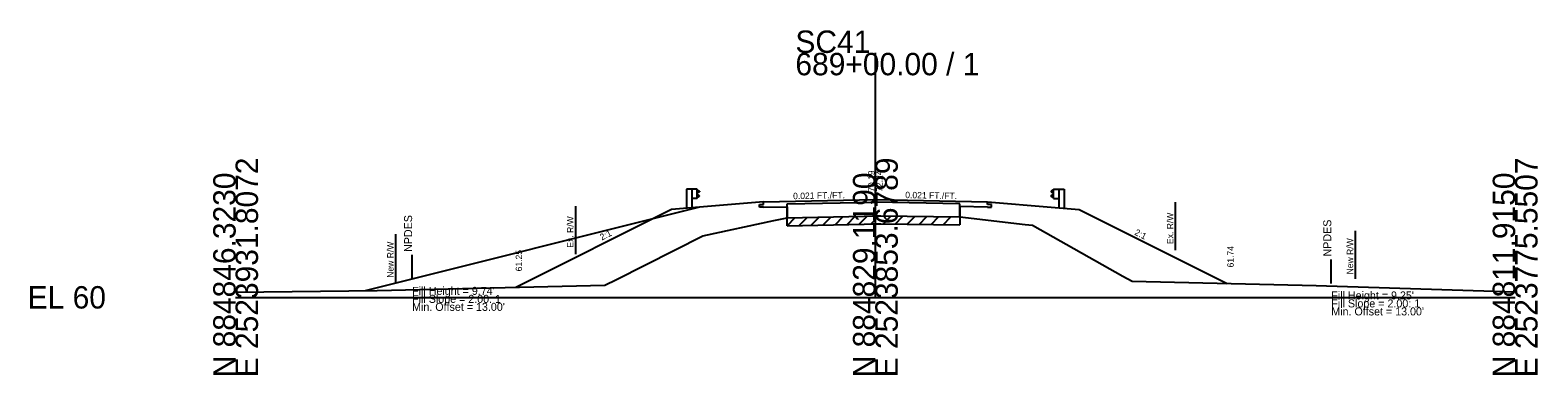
# Model space of a CAD drawing. Extents: x -26 to 183, y -10 to 24021.
# Drawn here: x -25.7 to 162.8, y 16490.3 to 16533.4 of the extents above; entities that cross this region are included whole.
import ezdxf

# ---------------------------------------------------------------- set-up
doc = ezdxf.new("R2010")
doc.units = 0
for name, color, linetype in [('RD_GPK_XS_Cell', 7, 'Continuous'), ('RD_XS_Base', 7, 'Continuous'), ('RD_XS_Buildup', 7, 'Continuous'), ('RD_XS_EarthShd', 7, 'Continuous'), ('RD_XS_ExGround', 7, 'Continuous'), ('RD_XS_ExPaveRet', 7, 'Continuous'), ('RD_XS_ExRW', 7, 'Continuous'), ('RD_XS_GR', 7, 'Continuous'), ('RD_XS_NewRW', 7, 'Continuous'), ('RD_XS_NPDES', 7, 'Continuous'), ('RD_XS_Pave', 7, 'Continuous'), ('RD_XS_TieSlope', 7, 'Continuous'), ('RD_XS_TX_Elev_EX', 7, 'Continuous'), ('RD_XS_TX_Elev_PR', 7, 'Continuous'), ('RD_XS_TX_Slope', 7, 'Continuous'), ('RD_XS_TX_Warning', 7, 'Continuous')]:
    doc.layers.add(name, color=color, linetype=linetype)

msp = doc.modelspace()

# ---------------------------------------------------------------- linework, layer by layer
at = {"layer": 'RD_GPK_XS_Cell'}
for p, q in [((80, 16500), (80, 16530.57)), ((0, 16500), (80, 16500)), ((80, 16500), (160, 16500))]:
    msp.add_line(p, q, dxfattribs=at)
at = {"layer": 'RD_XS_Base'}
for p, q in [((66, 16511.27), (68.96, 16511.33)), ((68.96, 16511.33), (68.96, 16509.94)), ((90.58, 16511.34), (90.58, 16510.05)), ((94, 16511.27), (90.58, 16511.34))]:
    msp.add_line(p, q, dxfattribs=at)
at = {"layer": 'RD_XS_Buildup'}
for p, q in [((68.96, 16511.69), (80, 16511.92)), ((68.96, 16509.94), (68.96, 16511.69)), ((90.58, 16511.7), (80, 16511.92)), ((90.58, 16510.05), (90.58, 16511.7))]:
    msp.add_line(p, q, dxfattribs=at)
at = {"layer": 'RD_XS_EarthShd'}
for p, q in [((66, 16511.95), (58, 16511.28)), ((94, 16511.95), (102, 16511.28)), ((58, 16511.28), (54.5, 16510.99)), ((102, 16511.28), (105.5, 16510.99))]:
    msp.add_line(p, q, dxfattribs=at)
at = {"layer": 'RD_XS_ExGround'}
for p, q in [((67.29, 16509.59), (68.96, 16509.94)), ((68.96, 16509.94), (78.58, 16510.16)), ((78.58, 16510.16), (79.65, 16510.19)), ((79.65, 16510.19), (80, 16510.19)), ((80, 16510.19), (80.67, 16510.18)), ((80.67, 16510.18), (90.58, 16510.05)), ((90.58, 16510.05), (98.72, 16509.13)), ((58.42, 16507.69), (67.29, 16509.59)), ((98.72, 16509.13), (99.65, 16509.01)), ((99.65, 16509.01), (110.95, 16502.65)), ((47.64, 16502.25), (58.42, 16507.69)), ((110.95, 16502.65), (112.09, 16502.01)), ((0, 16500.64), (17.69, 16500.85)), ((17.69, 16500.85), (46.18, 16501.51)), ((46.18, 16501.51), (47.64, 16502.25)), ((112.09, 16502.01), (135.13, 16501.48)), ((135.13, 16501.48), (160, 16500.69))]:
    msp.add_line(p, q, dxfattribs=at)
at = {"layer": 'RD_XS_ExPaveRet'}
for p, q in [((68.96, 16508.94), (69.98, 16509.97)), ((68.96, 16508.94), (68.96, 16509.94)), ((70.46, 16508.98), (71.48, 16510)), ((71.96, 16509.01), (72.98, 16510.04)), ((73.46, 16509.05), (74.48, 16510.07)), ((74.96, 16509.08), (75.98, 16510.11)), ((76.46, 16509.12), (77.48, 16510.14)), ((77.96, 16509.15), (78.98, 16510.17)), ((79.46, 16509.19), (80.45, 16510.18)), ((80.96, 16509.17), (81.94, 16510.16)), ((82.46, 16509.16), (83.44, 16510.14)), ((83.96, 16509.14), (84.94, 16510.12)), ((85.46, 16509.12), (86.44, 16510.11)), ((86.96, 16509.1), (87.94, 16510.09)), ((88.46, 16509.08), (89.44, 16510.07)), ((90.58, 16510.05), (90.58, 16509.05)), ((68.96, 16508.94), (78.58, 16509.16)), ((78.58, 16509.16), (79.65, 16509.19)), ((79.65, 16509.19), (80, 16509.19)), ((80, 16509.19), (80.67, 16509.18)), ((80.67, 16509.18), (90.58, 16509.05))]:
    msp.add_line(p, q, dxfattribs=at)
at = {"layer": 'RD_XS_ExRW'}
for p, q in [((117.5, 16511.89), (117.5, 16505.89)), ((42.5, 16511.42), (42.5, 16505.42))]:
    msp.add_line(p, q, dxfattribs=at)
at = {"layer": 'RD_XS_GR'}
for p, q in [((56.4, 16513.53), (56.4, 16511.15)), ((57.06, 16513.53), (56.4, 16513.53)), ((57.06, 16513.53), (57.06, 16511.2)), ((57.73, 16513.53), (57.06, 16513.53)), ((57.73, 16512.36), (57.06, 16512.36)), ((57.73, 16512.36), (57.73, 16513.53)), ((57.73, 16513.46), (58, 16513.26)), ((58, 16513.21), (57.73, 16513.01)), ((58, 16512.69), (57.73, 16512.89)), ((57.73, 16512.44), (58, 16512.64)), ((58, 16513.26), (58, 16513.21)), ((58, 16512.64), (58, 16512.69)), ((102.27, 16513.46), (102, 16513.26)), ((102, 16513.26), (102, 16513.21)), ((102, 16513.21), (102.27, 16513.01)), ((102, 16512.69), (102.27, 16512.89)), ((102, 16512.64), (102, 16512.69)), ((102.27, 16512.44), (102, 16512.64)), ((102.27, 16512.36), (102.27, 16513.53)), ((102.27, 16513.53), (102.94, 16513.53)), ((102.27, 16512.36), (102.94, 16512.36)), ((102.94, 16513.53), (102.94, 16511.2)), ((102.94, 16513.53), (103.6, 16513.53)), ((103.6, 16513.53), (103.6, 16511.15))]:
    msp.add_line(p, q, dxfattribs=at)
at = {"layer": 'RD_XS_NewRW'}
for p, q in [((140, 16508.32), (140, 16502.32)), ((20, 16507.9), (20, 16501.9))]:
    msp.add_line(p, q, dxfattribs=at)
at = {"layer": 'RD_XS_NPDES'}
for p, q in [((22.07, 16502.31), (22.07, 16505.31)), ((137.01, 16501.74), (137.01, 16504.74))]:
    msp.add_line(p, q, dxfattribs=at)
at = {"layer": 'RD_XS_Pave'}
for p, q in [((66, 16511.95), (80, 16512.24)), ((66, 16511.63), (66, 16511.95)), ((80, 16512.24), (94, 16511.95)), ((94, 16511.63), (94, 16511.95)), ((58, 16511.28), (16.21, 16500.83)), ((65.5, 16511.62), (66, 16511.63)), ((65.5, 16511.26), (65.5, 16511.62)), ((66, 16511.27), (65.5, 16511.26)), ((94.5, 16511.62), (94, 16511.63)), ((94, 16511.27), (94.5, 16511.26)), ((94.5, 16511.26), (94.5, 16511.62))]:
    msp.add_line(p, q, dxfattribs=at)
at = {"layer": 'RD_XS_TieSlope'}
for p, q in [((54.5, 16510.99), (35.02, 16501.25)), ((105.5, 16510.99), (124.01, 16501.74))]:
    msp.add_line(p, q, dxfattribs=at)

# ---------------------------------------------------------------- texts
at = {"layer": 'RD_GPK_XS_Cell'}
for s, p in [('SC41', (70, 16530.57)), ('689+00.00 / 1', (70, 16527.77)), ('EL 60', (-26, 16498.6))]:
    msp.add_text(s, height=2.8, dxfattribs=at).set_placement(p)
for s, p in [('N 884846.3230', (0, 16490)), ('E 2523931.8072', (2.8, 16490)), ('N 884829.1190', (80, 16490)), ('E 2523853.6789', (82.8, 16490)), ('N 884811.9150', (160, 16490)), ('E 2523775.5507', (162.8, 16490))]:
    msp.add_text(s, height=2.8, rotation=90, dxfattribs=at).set_placement(p)
at = {"layer": 'RD_XS_ExRW'}
for p in [(42.25, 16506.21), (117.25, 16506.67)]:
    msp.add_text('Ex. R/W ', height=0.8, rotation=90, dxfattribs=at).set_placement(p)
at = {"layer": 'RD_XS_NewRW'}
for p in [(19.75, 16502.45), (139.75, 16502.87)]:
    msp.add_text('New R/W ', height=0.8, rotation=90, dxfattribs=at).set_placement(p)
at = {"layer": 'RD_XS_TX_Elev_EX'}
msp.add_text('70.19', height=0.8, rotation=90, dxfattribs=at).set_placement((79.9, 16513.19))
at = {"layer": 'RD_XS_TX_Elev_PR'}
for s, p in [('72.24', (80.9, 16513.19)), ('61.74', (124.81, 16503.74)), ('61.25', (35.82, 16503.25))]:
    msp.add_text(s, height=0.8, rotation=90, dxfattribs=at).set_placement(p)
at = {"layer": 'RD_XS_TX_Slope'}
for s, rotation, p in [('0.021 FT./FT.', 1.1916, (69.72, 16512.27)), ('0.021 FT./FT.', 358.8084, (83.73, 16512.41)), ('2:1', 26.5651, (45.78, 16507.1)), ('2:1', 333.4349, (112.33, 16507.87))]:
    msp.add_text(s, height=0.8, rotation=rotation, dxfattribs=at).set_placement(p)
at = {"layer": 'RD_XS_TX_Warning'}
for p in [(22.07, 16505.31), (137.01, 16504.74)]:
    msp.add_text(' NPDES', height=1, rotation=90, dxfattribs=at).set_placement(p)
for s, p in [("Fill Height = 9.74' ", (22.07, 16500.31)), ("Fill Height = 9.25' ", (137.01, 16499.74)), ('Fill Slope = 2.00: 1', (22.07, 16499.31)), ("Min. Offset = 13.00' ", (22.07, 16498.31)), ('Fill Slope = 2.00: 1', (137.01, 16498.74)), ("Min. Offset = 13.00' ", (137.01, 16497.74))]:
    msp.add_text(s, height=1, dxfattribs=at).set_placement(p)

doc.saveas('drawing.dxf')
